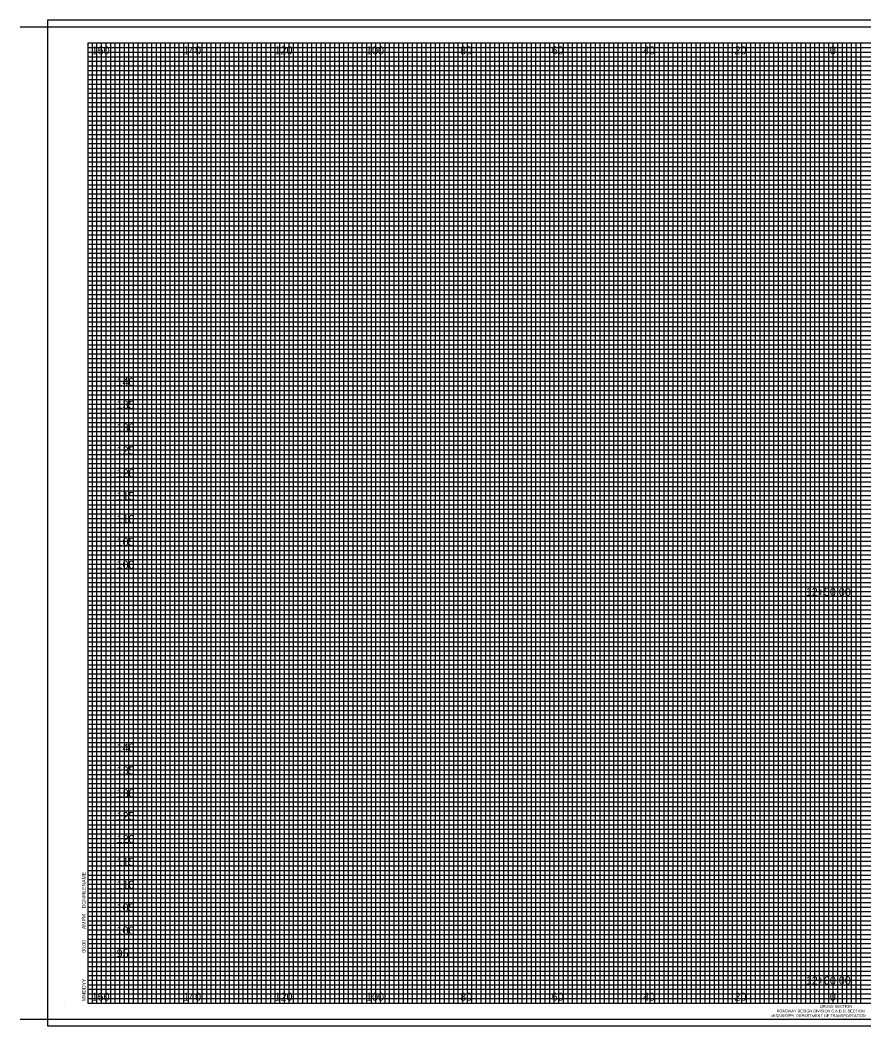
# Model space of a CAD drawing. Extents: x 21281 to 21817, y 6470 to 8300.
# Drawn here: x 21465 to 21649.5, y 6929.8 to 7149.8 of the extents above; entities that cross this region are included whole.
import ezdxf

# ---------------------------------------------------------------- set-up
doc = ezdxf.new("R2010")
doc.units = 0
for name, color, linetype in [('SHEET_BORDER', 7, 'Continuous'), ('SHEET_BORDER_TX', 7, 'Continuous'), ('SHEET_DATE_DGN_TX', 7, 'Continuous'), ('SHEET_PLOTTING_SHAPE', 7, 'Continuous'), ('XS_SHEET_LABELS_ELEVATION', 7, 'Continuous'), ('XS_SHEET_LABELS_OFFSET', 7, 'Continuous'), ('XS_SHEET_LABELS_STATION', 7, 'Continuous'), ('XS_SHEET_MAJOR_GRIDS', 7, 'Continuous'), ('XS_SHEET_MEDIUM_GRIDS', 7, 'Continuous'), ('XS_SHEET_MINOR_GRIDS', 7, 'Continuous')]:
    doc.layers.add(name, color=color, linetype=linetype)

msp = doc.modelspace()

# ---------------------------------------------------------------- linework, layer by layer
at = {"layer": 'SHEET_BORDER'}
for p, q in [((21465.04, 7148.34), (21817.04, 7148.34)), ((21479.84, 7144.84), (21814.84, 7144.84)), ((21479.84, 7144.84), (21479.84, 6934.84)), ((21623.84, 6934.84), (21623.84, 7144.84)), ((21474.84, 6934.84), (21474.84, 6934.84)), ((21479.84, 6934.84), (21814.84, 6934.84)), ((21465.04, 6931.34), (21817.04, 6931.34))]:
    msp.add_line(p, q, dxfattribs=at)
at = {"layer": 'SHEET_PLOTTING_SHAPE'}
msp.add_lwpolyline([(21471.04, 6929.84), (21817.04, 6929.84), (21817.04, 7149.84), (21471.04, 7149.84)], close=True, dxfattribs=at)
at = {"layer": 'XS_SHEET_MAJOR_GRIDS'}
for p, q in [((21484.84, 6934.84), (21484.84, 7144.84)), ((21494.84, 6934.84), (21494.84, 7144.84)), ((21504.84, 6934.84), (21504.84, 7144.84)), ((21514.84, 6934.84), (21514.84, 7144.84)), ((21524.84, 6934.84), (21524.84, 7144.84)), ((21534.84, 6934.84), (21534.84, 7144.84)), ((21544.84, 6934.84), (21544.84, 7144.84)), ((21554.84, 6934.84), (21554.84, 7144.84)), ((21564.84, 6934.84), (21564.84, 7144.84)), ((21574.84, 6934.84), (21574.84, 7144.84)), ((21584.84, 6934.84), (21584.84, 7144.84)), ((21594.84, 6934.84), (21594.84, 7144.84)), ((21604.84, 6934.84), (21604.84, 7144.84)), ((21614.84, 6934.84), (21614.84, 7144.84)), ((21624.84, 6934.84), (21624.84, 7144.84)), ((21634.84, 6934.84), (21634.84, 7144.84)), ((21644.84, 6934.84), (21644.84, 7144.84)), ((21479.84, 7134.84), (21814.84, 7134.84)), ((21479.84, 7124.84), (21814.84, 7124.84)), ((21479.84, 7114.84), (21814.84, 7114.84)), ((21479.84, 7104.84), (21814.84, 7104.84)), ((21479.84, 7094.84), (21814.84, 7094.84)), ((21479.84, 7084.84), (21814.84, 7084.84)), ((21479.84, 7074.84), (21814.84, 7074.84)), ((21479.84, 7064.84), (21814.84, 7064.84)), ((21479.84, 7054.84), (21814.84, 7054.84)), ((21479.84, 7044.84), (21814.84, 7044.84)), ((21479.84, 7034.84), (21814.84, 7034.84)), ((21479.84, 7024.84), (21814.84, 7024.84)), ((21479.84, 7014.84), (21814.84, 7014.84)), ((21479.84, 7004.84), (21814.84, 7004.84)), ((21479.84, 6994.84), (21814.84, 6994.84)), ((21479.84, 6984.84), (21814.84, 6984.84)), ((21479.84, 6974.84), (21814.84, 6974.84)), ((21479.84, 6964.84), (21814.84, 6964.84)), ((21479.84, 6954.84), (21814.84, 6954.84)), ((21479.84, 6944.84), (21814.84, 6944.84))]:
    msp.add_line(p, q, dxfattribs=at)
at = {"layer": 'XS_SHEET_MEDIUM_GRIDS'}
for p, q in [((21489.84, 6934.84), (21489.84, 7144.84)), ((21499.84, 6934.84), (21499.84, 7144.84)), ((21509.84, 6934.84), (21509.84, 7144.84)), ((21519.84, 6934.84), (21519.84, 7144.84)), ((21529.84, 6934.84), (21529.84, 7144.84)), ((21539.84, 6934.84), (21539.84, 7144.84)), ((21549.84, 6934.84), (21549.84, 7144.84)), ((21559.84, 6934.84), (21559.84, 7144.84)), ((21569.84, 6934.84), (21569.84, 7144.84)), ((21579.84, 6934.84), (21579.84, 7144.84)), ((21589.84, 6934.84), (21589.84, 7144.84)), ((21599.84, 6934.84), (21599.84, 7144.84)), ((21609.84, 6934.84), (21609.84, 7144.84)), ((21619.84, 6934.84), (21619.84, 7144.84)), ((21629.84, 6934.84), (21629.84, 7144.84)), ((21639.84, 6934.84), (21639.84, 7144.84)), ((21479.84, 7139.84), (21787.84, 7139.84)), ((21479.84, 7129.84), (21814.84, 7129.84)), ((21479.84, 7119.84), (21814.84, 7119.84)), ((21479.84, 7109.84), (21814.84, 7109.84)), ((21479.84, 7099.84), (21814.84, 7099.84)), ((21479.84, 7089.84), (21814.84, 7089.84)), ((21479.84, 7079.84), (21814.84, 7079.84)), ((21479.84, 7069.84), (21814.84, 7069.84)), ((21479.84, 7059.84), (21814.84, 7059.84)), ((21479.84, 7049.84), (21814.84, 7049.84)), ((21479.84, 7039.84), (21814.84, 7039.84)), ((21479.84, 7029.84), (21814.84, 7029.84)), ((21479.84, 7019.84), (21814.84, 7019.84)), ((21479.84, 7009.84), (21814.84, 7009.84)), ((21479.84, 6999.84), (21814.84, 6999.84)), ((21479.84, 6989.84), (21814.84, 6989.84)), ((21479.84, 6979.84), (21814.84, 6979.84)), ((21479.84, 6969.84), (21814.84, 6969.84)), ((21479.84, 6959.84), (21814.84, 6959.84)), ((21479.84, 6949.84), (21814.84, 6949.84)), ((21479.84, 6939.84), (21804.84, 6939.84))]:
    msp.add_line(p, q, dxfattribs=at)
at = {"layer": 'XS_SHEET_MINOR_GRIDS'}
for p, q in [((21479.84, 7143.84), (21787.84, 7143.84)), ((21480.84, 6934.84), (21480.84, 7144.84)), ((21481.84, 6934.84), (21481.84, 7144.84)), ((21482.84, 6934.84), (21482.84, 7144.84)), ((21483.84, 6934.84), (21483.84, 7144.84)), ((21485.84, 6934.84), (21485.84, 7144.84)), ((21486.84, 6934.84), (21486.84, 7144.84)), ((21487.84, 6934.84), (21487.84, 7144.84)), ((21488.84, 6934.84), (21488.84, 7144.84)), ((21490.84, 6934.84), (21490.84, 7144.84)), ((21491.84, 6934.84), (21491.84, 7144.84)), ((21492.84, 6934.84), (21492.84, 7144.84)), ((21493.84, 6934.84), (21493.84, 7144.84)), ((21495.84, 6934.84), (21495.84, 7144.84)), ((21496.84, 6934.84), (21496.84, 7144.84)), ((21497.84, 6934.84), (21497.84, 7144.84)), ((21498.84, 6934.84), (21498.84, 7144.84)), ((21500.84, 6934.84), (21500.84, 7144.84)), ((21501.84, 6934.84), (21501.84, 7144.84)), ((21502.84, 6934.84), (21502.84, 7144.84)), ((21503.84, 6934.84), (21503.84, 7144.84)), ((21505.84, 6934.84), (21505.84, 7144.84)), ((21506.84, 6934.84), (21506.84, 7144.84)), ((21507.84, 6934.84), (21507.84, 7144.84)), ((21508.84, 6934.84), (21508.84, 7144.84)), ((21510.84, 6934.84), (21510.84, 7144.84)), ((21511.84, 6934.84), (21511.84, 7144.84)), ((21512.84, 6934.84), (21512.84, 7144.84)), ((21513.84, 6934.84), (21513.84, 7144.84)), ((21515.84, 6934.84), (21515.84, 7144.84)), ((21516.84, 6934.84), (21516.84, 7144.84)), ((21517.84, 6934.84), (21517.84, 7144.84)), ((21518.84, 6934.84), (21518.84, 7144.84)), ((21520.84, 6934.84), (21520.84, 7144.84)), ((21521.84, 6934.84), (21521.84, 7144.84)), ((21522.84, 6934.84), (21522.84, 7144.84)), ((21523.84, 6934.84), (21523.84, 7144.84)), ((21525.84, 6934.84), (21525.84, 7144.84)), ((21526.84, 6934.84), (21526.84, 7144.84)), ((21527.84, 6934.84), (21527.84, 7144.84)), ((21528.84, 6934.84), (21528.84, 7144.84)), ((21530.84, 6934.84), (21530.84, 7144.84)), ((21531.84, 6934.84), (21531.84, 7144.84)), ((21532.84, 6934.84), (21532.84, 7144.84)), ((21533.84, 6934.84), (21533.84, 7144.84)), ((21535.84, 6934.84), (21535.84, 7144.84)), ((21536.84, 6934.84), (21536.84, 7144.84)), ((21537.84, 6934.84), (21537.84, 7144.84)), ((21538.84, 6934.84), (21538.84, 7144.84)), ((21540.84, 6934.84), (21540.84, 7144.84)), ((21541.84, 6934.84), (21541.84, 7144.84)), ((21542.84, 6934.84), (21542.84, 7144.84)), ((21543.84, 6934.84), (21543.84, 7144.84)), ((21545.84, 6934.84), (21545.84, 7144.84)), ((21546.84, 6934.84), (21546.84, 7144.84)), ((21547.84, 6934.84), (21547.84, 7144.84)), ((21548.84, 6934.84), (21548.84, 7144.84)), ((21550.84, 6934.84), (21550.84, 7144.84)), ((21551.84, 6934.84), (21551.84, 7144.84)), ((21552.84, 6934.84), (21552.84, 7144.84)), ((21553.84, 6934.84), (21553.84, 7144.84)), ((21555.84, 6934.84), (21555.84, 7144.84)), ((21556.84, 6934.84), (21556.84, 7144.84)), ((21557.84, 6934.84), (21557.84, 7144.84)), ((21558.84, 6934.84), (21558.84, 7144.84)), ((21560.84, 6934.84), (21560.84, 7144.84)), ((21561.84, 6934.84), (21561.84, 7144.84)), ((21562.84, 6934.84), (21562.84, 7144.84)), ((21563.84, 6934.84), (21563.84, 7144.84)), ((21565.84, 6934.84), (21565.84, 7144.84)), ((21566.84, 6934.84), (21566.84, 7144.84)), ((21567.84, 6934.84), (21567.84, 7144.84)), ((21568.84, 6934.84), (21568.84, 7144.84)), ((21570.84, 6934.84), (21570.84, 7144.84)), ((21571.84, 6934.84), (21571.84, 7144.84)), ((21572.84, 6934.84), (21572.84, 7144.84)), ((21573.84, 6934.84), (21573.84, 7144.84)), ((21575.84, 6934.84), (21575.84, 7144.84)), ((21576.84, 6934.84), (21576.84, 7144.84)), ((21577.84, 6934.84), (21577.84, 7144.84)), ((21578.84, 6934.84), (21578.84, 7144.84)), ((21580.84, 6934.84), (21580.84, 7144.84)), ((21581.84, 6934.84), (21581.84, 7144.84)), ((21582.84, 6934.84), (21582.84, 7144.84)), ((21583.84, 6934.84), (21583.84, 7144.84)), ((21585.84, 6934.84), (21585.84, 7144.84)), ((21586.84, 6934.84), (21586.84, 7144.84)), ((21587.84, 6934.84), (21587.84, 7144.84)), ((21588.84, 6934.84), (21588.84, 7144.84)), ((21590.84, 6934.84), (21590.84, 7144.84)), ((21591.84, 6934.84), (21591.84, 7144.84)), ((21592.84, 6934.84), (21592.84, 7144.84)), ((21593.84, 6934.84), (21593.84, 7144.84)), ((21595.84, 6934.84), (21595.84, 7144.84)), ((21596.84, 6934.84), (21596.84, 7144.84)), ((21597.84, 6934.84), (21597.84, 7144.84)), ((21598.84, 6934.84), (21598.84, 7144.84)), ((21600.84, 6934.84), (21600.84, 7144.84)), ((21601.84, 6934.84), (21601.84, 7144.84)), ((21602.84, 6934.84), (21602.84, 7144.84)), ((21603.84, 6934.84), (21603.84, 7144.84)), ((21605.84, 6934.84), (21605.84, 7144.84)), ((21606.84, 6934.84), (21606.84, 7144.84)), ((21607.84, 6934.84), (21607.84, 7144.84)), ((21608.84, 6934.84), (21608.84, 7144.84)), ((21610.84, 6934.84), (21610.84, 7144.84)), ((21611.84, 6934.84), (21611.84, 7144.84)), ((21612.84, 6934.84), (21612.84, 7144.84)), ((21613.84, 6934.84), (21613.84, 7144.84)), ((21615.84, 6934.84), (21615.84, 7144.84)), ((21616.84, 6934.84), (21616.84, 7144.84)), ((21617.84, 6934.84), (21617.84, 7144.84)), ((21618.84, 6934.84), (21618.84, 7144.84)), ((21620.84, 6934.84), (21620.84, 7144.84)), ((21621.84, 6934.84), (21621.84, 7144.84)), ((21622.84, 6934.84), (21622.84, 7144.84)), ((21625.84, 6934.84), (21625.84, 7144.84)), ((21626.84, 6934.84), (21626.84, 7144.84)), ((21627.84, 6934.84), (21627.84, 7144.84)), ((21628.84, 6934.84), (21628.84, 7144.84)), ((21630.84, 6934.84), (21630.84, 7144.84)), ((21631.84, 6934.84), (21631.84, 7144.84)), ((21632.84, 6934.84), (21632.84, 7144.84)), ((21633.84, 6934.84), (21633.84, 7144.84)), ((21635.84, 6934.84), (21635.84, 7144.84)), ((21636.84, 6934.84), (21636.84, 7144.84)), ((21637.84, 6934.84), (21637.84, 7144.84)), ((21638.84, 6934.84), (21638.84, 7144.84)), ((21640.84, 6934.84), (21640.84, 7144.84)), ((21641.84, 6934.84), (21641.84, 7144.84)), ((21642.84, 6934.84), (21642.84, 7144.84)), ((21643.84, 6934.84), (21643.84, 7144.84)), ((21645.84, 6934.84), (21645.84, 7144.84)), ((21646.84, 6934.84), (21646.84, 7144.84)), ((21647.84, 6934.84), (21647.84, 7144.84)), ((21648.84, 6934.84), (21648.84, 7144.84)), ((21479.84, 7142.84), (21787.84, 7142.84)), ((21479.84, 7141.84), (21787.84, 7141.84)), ((21479.84, 7140.84), (21787.84, 7140.84)), ((21479.84, 7138.84), (21787.84, 7138.84)), ((21479.84, 7137.84), (21787.84, 7137.84)), ((21479.84, 7136.84), (21787.84, 7136.84)), ((21479.84, 7135.84), (21814.84, 7135.84)), ((21479.84, 7133.84), (21814.84, 7133.84)), ((21479.84, 7132.84), (21814.84, 7132.84)), ((21479.84, 7131.84), (21814.84, 7131.84)), ((21479.84, 7130.84), (21814.84, 7130.84)), ((21479.84, 7128.84), (21814.84, 7128.84)), ((21479.84, 7127.84), (21814.84, 7127.84)), ((21479.84, 7126.84), (21814.84, 7126.84)), ((21479.84, 7125.84), (21814.84, 7125.84)), ((21479.84, 7123.84), (21814.84, 7123.84)), ((21479.84, 7122.84), (21814.84, 7122.84)), ((21479.84, 7121.84), (21814.84, 7121.84)), ((21479.84, 7120.84), (21814.84, 7120.84)), ((21479.84, 7118.84), (21814.84, 7118.84)), ((21479.84, 7117.84), (21814.84, 7117.84)), ((21479.84, 7116.84), (21814.84, 7116.84)), ((21479.84, 7115.84), (21814.84, 7115.84)), ((21479.84, 7113.84), (21814.84, 7113.84)), ((21479.84, 7112.84), (21814.84, 7112.84)), ((21479.84, 7111.84), (21814.84, 7111.84)), ((21479.84, 7110.84), (21814.84, 7110.84)), ((21479.84, 7108.84), (21814.84, 7108.84)), ((21479.84, 7107.84), (21814.84, 7107.84)), ((21479.84, 7106.84), (21814.84, 7106.84)), ((21479.84, 7105.84), (21814.84, 7105.84)), ((21479.84, 7103.84), (21814.84, 7103.84)), ((21479.84, 7102.84), (21814.84, 7102.84)), ((21479.84, 7101.84), (21814.84, 7101.84)), ((21479.84, 7100.84), (21814.84, 7100.84)), ((21479.84, 7098.84), (21814.84, 7098.84)), ((21479.84, 7097.84), (21814.84, 7097.84)), ((21479.84, 7096.84), (21814.84, 7096.84)), ((21479.84, 7095.84), (21814.84, 7095.84)), ((21479.84, 7093.84), (21814.84, 7093.84)), ((21479.84, 7092.84), (21814.84, 7092.84)), ((21479.84, 7091.84), (21814.84, 7091.84)), ((21479.84, 7090.84), (21814.84, 7090.84)), ((21479.84, 7088.84), (21814.84, 7088.84)), ((21479.84, 7087.84), (21814.84, 7087.84)), ((21479.84, 7086.84), (21814.84, 7086.84)), ((21479.84, 7085.84), (21814.84, 7085.84)), ((21479.84, 7083.84), (21814.84, 7083.84)), ((21479.84, 7082.84), (21814.84, 7082.84)), ((21479.84, 7081.84), (21814.84, 7081.84)), ((21479.84, 7080.84), (21814.84, 7080.84)), ((21479.84, 7078.84), (21814.84, 7078.84)), ((21479.84, 7077.84), (21814.84, 7077.84)), ((21479.84, 7076.84), (21814.84, 7076.84)), ((21479.84, 7075.84), (21814.84, 7075.84)), ((21479.84, 7073.84), (21814.84, 7073.84)), ((21479.84, 7072.84), (21814.84, 7072.84)), ((21479.84, 7071.84), (21814.84, 7071.84)), ((21479.84, 7070.84), (21814.84, 7070.84)), ((21479.84, 7068.84), (21814.84, 7068.84)), ((21479.84, 7067.84), (21814.84, 7067.84)), ((21479.84, 7066.84), (21814.84, 7066.84)), ((21479.84, 7065.84), (21814.84, 7065.84)), ((21479.84, 7063.84), (21814.84, 7063.84)), ((21479.84, 7062.84), (21814.84, 7062.84)), ((21479.84, 7061.84), (21814.84, 7061.84)), ((21479.84, 7060.84), (21814.84, 7060.84)), ((21479.84, 7058.84), (21814.84, 7058.84)), ((21479.84, 7057.84), (21814.84, 7057.84)), ((21479.84, 7056.84), (21814.84, 7056.84)), ((21479.84, 7055.84), (21814.84, 7055.84)), ((21479.84, 7053.84), (21814.84, 7053.84)), ((21479.84, 7052.84), (21814.84, 7052.84)), ((21479.84, 7051.84), (21814.84, 7051.84)), ((21479.84, 7050.84), (21814.84, 7050.84)), ((21479.84, 7048.84), (21814.84, 7048.84)), ((21479.84, 7047.84), (21814.84, 7047.84)), ((21479.84, 7046.84), (21814.84, 7046.84)), ((21479.84, 7045.84), (21814.84, 7045.84)), ((21479.84, 7043.84), (21814.84, 7043.84)), ((21479.84, 7042.84), (21814.84, 7042.84)), ((21479.84, 7041.84), (21814.84, 7041.84)), ((21479.84, 7040.84), (21814.84, 7040.84)), ((21479.84, 7038.84), (21814.84, 7038.84)), ((21479.84, 7037.84), (21814.84, 7037.84)), ((21479.84, 7036.84), (21814.84, 7036.84)), ((21479.84, 7035.84), (21814.84, 7035.84)), ((21479.84, 7033.84), (21814.84, 7033.84)), ((21479.84, 7032.84), (21814.84, 7032.84)), ((21479.84, 7031.84), (21814.84, 7031.84)), ((21479.84, 7030.84), (21814.84, 7030.84)), ((21479.84, 7028.84), (21814.84, 7028.84)), ((21479.84, 7027.84), (21814.84, 7027.84)), ((21479.84, 7026.84), (21814.84, 7026.84)), ((21479.84, 7025.84), (21814.84, 7025.84)), ((21479.84, 7023.84), (21814.84, 7023.84)), ((21479.84, 7022.84), (21814.84, 7022.84)), ((21479.84, 7021.84), (21814.84, 7021.84)), ((21479.84, 7020.84), (21814.84, 7020.84)), ((21479.84, 7018.84), (21814.84, 7018.84)), ((21479.84, 7017.84), (21814.84, 7017.84)), ((21479.84, 7016.84), (21814.84, 7016.84)), ((21479.84, 7015.84), (21814.84, 7015.84)), ((21479.84, 7013.84), (21814.84, 7013.84)), ((21479.84, 7012.84), (21814.84, 7012.84)), ((21479.84, 7011.84), (21814.84, 7011.84)), ((21479.84, 7010.84), (21814.84, 7010.84)), ((21479.84, 7008.84), (21814.84, 7008.84)), ((21479.84, 7007.84), (21814.84, 7007.84)), ((21479.84, 7006.84), (21814.84, 7006.84)), ((21479.84, 7005.84), (21814.84, 7005.84)), ((21479.84, 7003.84), (21814.84, 7003.84)), ((21479.84, 7002.84), (21814.84, 7002.84)), ((21479.84, 7001.84), (21814.84, 7001.84)), ((21479.84, 7000.84), (21814.84, 7000.84)), ((21479.84, 6998.84), (21814.84, 6998.84)), ((21479.84, 6997.84), (21814.84, 6997.84)), ((21479.84, 6996.84), (21814.84, 6996.84)), ((21479.84, 6995.84), (21814.84, 6995.84)), ((21479.84, 6993.84), (21814.84, 6993.84)), ((21479.84, 6992.84), (21814.84, 6992.84)), ((21479.84, 6991.84), (21814.84, 6991.84)), ((21479.84, 6990.84), (21814.84, 6990.84)), ((21479.84, 6988.84), (21814.84, 6988.84)), ((21479.84, 6987.84), (21814.84, 6987.84)), ((21479.84, 6986.84), (21814.84, 6986.84)), ((21479.84, 6985.84), (21814.84, 6985.84)), ((21479.84, 6983.84), (21814.84, 6983.84)), ((21479.84, 6982.84), (21814.84, 6982.84)), ((21479.84, 6981.84), (21814.84, 6981.84)), ((21479.84, 6980.84), (21814.84, 6980.84)), ((21479.84, 6978.84), (21814.84, 6978.84)), ((21479.84, 6977.84), (21814.84, 6977.84)), ((21479.84, 6976.84), (21814.84, 6976.84)), ((21479.84, 6975.84), (21814.84, 6975.84)), ((21479.84, 6973.84), (21814.84, 6973.84)), ((21479.84, 6972.84), (21814.84, 6972.84)), ((21479.84, 6971.84), (21814.84, 6971.84)), ((21479.84, 6970.84), (21814.84, 6970.84)), ((21479.84, 6968.84), (21814.84, 6968.84)), ((21479.84, 6967.84), (21814.84, 6967.84)), ((21479.84, 6966.84), (21814.84, 6966.84)), ((21479.84, 6965.84), (21814.84, 6965.84)), ((21479.84, 6963.84), (21814.84, 6963.84)), ((21479.84, 6962.84), (21814.84, 6962.84)), ((21479.84, 6961.84), (21814.84, 6961.84)), ((21479.84, 6960.84), (21814.84, 6960.84)), ((21479.84, 6958.84), (21814.84, 6958.84)), ((21479.84, 6957.84), (21814.84, 6957.84)), ((21479.84, 6956.84), (21814.84, 6956.84)), ((21479.84, 6955.84), (21814.84, 6955.84)), ((21479.84, 6955.84), (21814.84, 6955.84)), ((21479.84, 6955.84), (21814.84, 6955.84)), ((21479.84, 6953.84), (21814.84, 6953.84)), ((21479.84, 6952.84), (21814.84, 6952.84)), ((21479.84, 6951.84), (21814.84, 6951.84)), ((21479.84, 6950.84), (21814.84, 6950.84)), ((21479.84, 6948.84), (21814.84, 6948.84)), ((21479.84, 6947.84), (21814.84, 6947.84)), ((21479.84, 6946.84), (21814.84, 6946.84)), ((21479.84, 6945.84), (21814.84, 6945.84)), ((21479.84, 6943.84), (21804.84, 6943.84)), ((21479.84, 6942.84), (21804.84, 6942.84)), ((21479.84, 6941.84), (21804.84, 6941.84)), ((21479.84, 6940.84), (21804.84, 6940.84)), ((21479.84, 6940.84), (21804.84, 6940.84)), ((21479.84, 6940.84), (21804.84, 6940.84)), ((21479.84, 6938.84), (21804.84, 6938.84)), ((21479.84, 6937.84), (21804.84, 6937.84)), ((21479.84, 6936.84), (21804.84, 6936.84)), ((21479.84, 6935.84), (21804.84, 6935.84))]:
    msp.add_line(p, q, dxfattribs=at)

# ---------------------------------------------------------------- texts
at = {"layer": 'SHEET_BORDER_TX'}
for s, height, p in [('CROSS SECTION', 0.62, (21639.87, 6933.81)), ('MISSISSIPPI  DEPARTMENT OF TRANSPORTATION', 0.61, (21629.27, 6931.75)), ('ROADWAY DESIGN DIVISION C.A.D.D. SECTION', 0.61, (21630.44, 6932.78))]:
    msp.add_text(s, height=height, dxfattribs=at).set_placement(p)
at = {"layer": 'SHEET_DATE_DGN_TX'}
for s, p in [('DGNFILENAME', (21479.37, 6955.54)), ('AMPM', (21479.37, 6951.02)), ('00:00', (21479.37, 6945.84)), ('MMDDYY', (21479.37, 6935.26))]:
    msp.add_text(s, height=0.8, rotation=90, dxfattribs=at).set_placement(p)
at = {"layer": 'XS_SHEET_LABELS_ELEVATION'}
for s, p in [('  140  ', (21484.84, 7069.84)), ('  135  ', (21484.84, 7064.84)), ('  130  ', (21484.84, 7059.84)), ('  125  ', (21484.84, 7054.84)), ('  120  ', (21484.84, 7049.84)), ('  115  ', (21484.84, 7044.84)), ('  110  ', (21484.84, 7039.84)), ('  105  ', (21484.84, 7034.84)), ('  100  ', (21484.84, 7029.84)), ('  140  ', (21484.84, 6989.84)), ('  135  ', (21484.84, 6984.84)), ('  130  ', (21484.84, 6979.84)), ('  125  ', (21484.84, 6974.84)), ('  120  ', (21484.84, 6969.84)), ('  115  ', (21484.84, 6964.84)), ('  110  ', (21484.84, 6959.84)), ('  105  ', (21484.84, 6954.84)), ('  100  ', (21484.84, 6949.84)), ('  95  ', (21484.84, 6944.84))]:
    msp.add_text(s, height=1.75, dxfattribs=at).set_placement(p)
at = {"layer": 'XS_SHEET_LABELS_OFFSET'}
for s, p in [('  160  ', (21479.4, 7142.34)), ('  140  ', (21499.39, 7142.34)), ('  120  ', (21519.39, 7142.34)), ('  100  ', (21539.39, 7142.34)), ('  80  ', (21559.95, 7142.34)), ('  60  ', (21579.97, 7142.34)), ('  40  ', (21599.95, 7142.34)), ('  20  ', (21619.95, 7142.34)), ('  0  ', (21640.81, 7142.34)), ('  0  ', (21640.81, 7142.34)), ('  160  ', (21479.4, 6935.34)), ('  140  ', (21499.39, 6935.34)), ('  120  ', (21519.39, 6935.34)), ('  100  ', (21539.39, 6935.34)), ('  80  ', (21559.95, 6935.34)), ('  60  ', (21579.97, 6935.34)), ('  40  ', (21599.95, 6935.34)), ('  20  ', (21619.95, 6935.34)), ('  0  ', (21640.81, 6935.34)), ('  0  ', (21640.81, 6935.34))]:
    msp.add_text(s, height=1.75, dxfattribs=at).set_placement(p)
at = {"layer": 'XS_SHEET_LABELS_STATION'}
for s, p in [('  12+50.00  ', (21635.54, 7023.89)), ('  12+00.00  ', (21635.54, 6938.89))]:
    msp.add_text(s, height=1.75, dxfattribs=at).set_placement(p)

doc.saveas('drawing.dxf')
